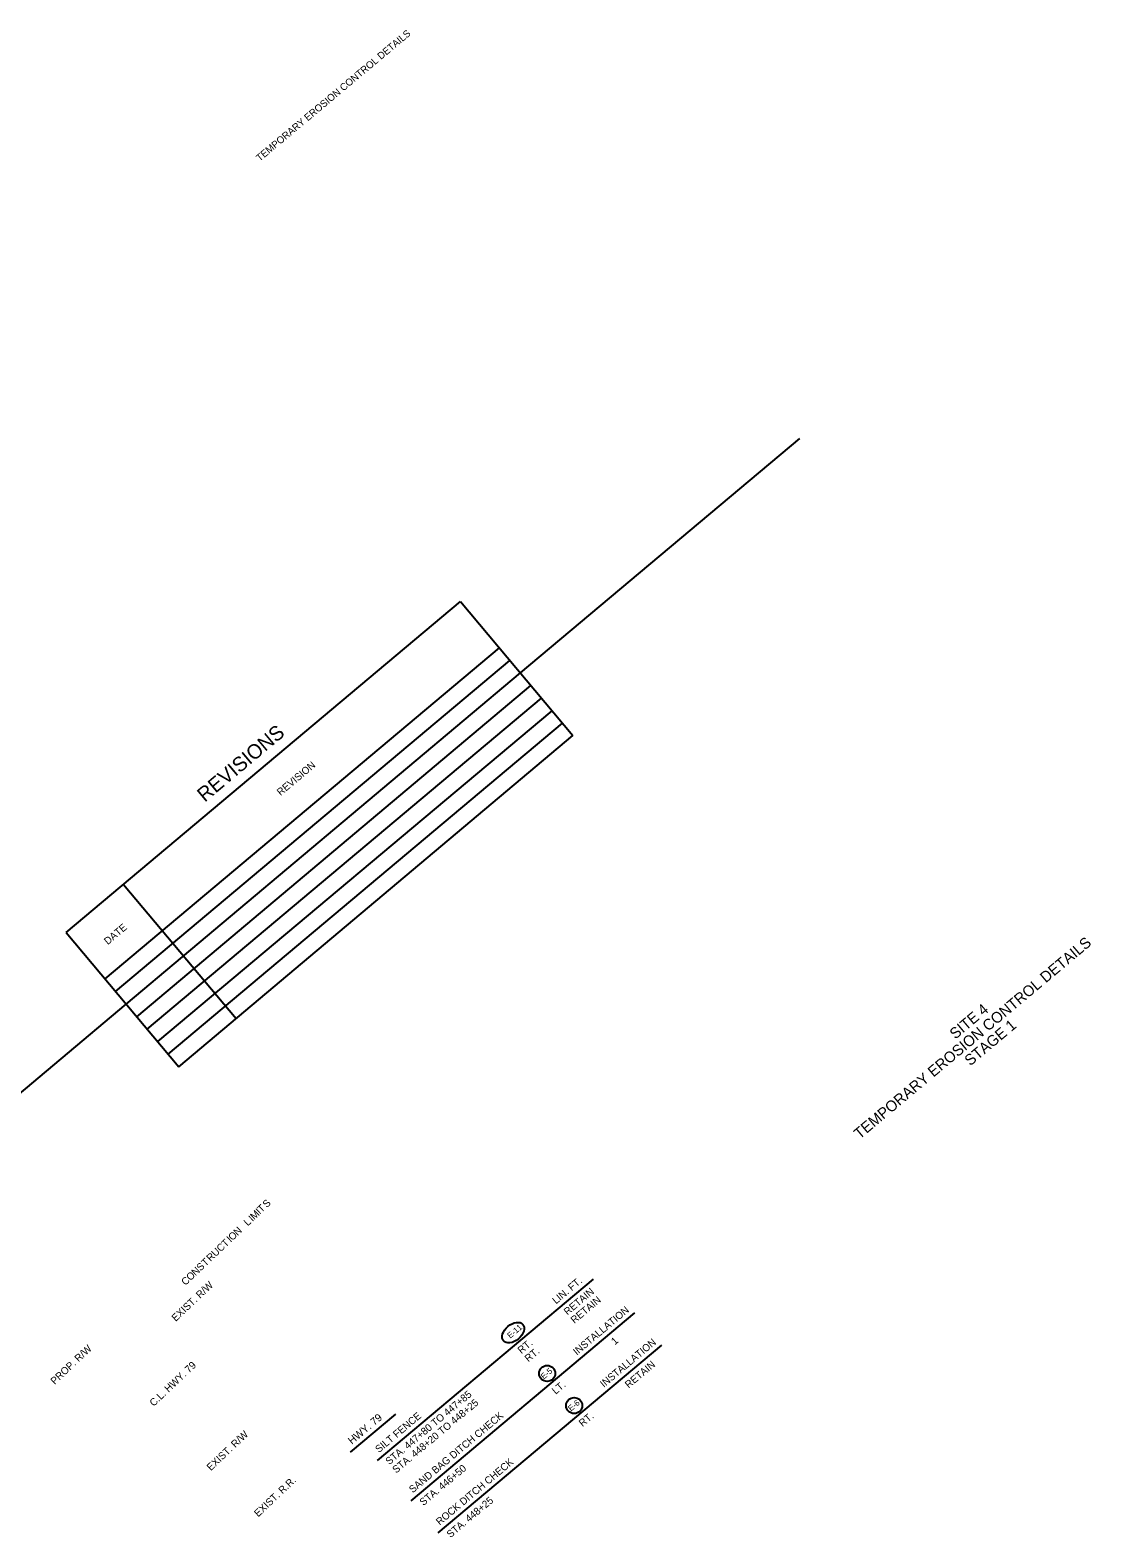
# Model space of a CAD drawing. Extents: x 1430270 to 1431940, y 1964864 to 1966264.
# Drawn here: x 1431064 to 1431940, y 1965020 to 1966264 of the extents above; entities that cross this region are included whole.
import ezdxf

# ---------------------------------------------------------------- set-up
doc = ezdxf.new("R2010")
doc.units = 0
for name, color, linetype in [('1', 7, 'Continuous'), ('44', 7, 'Continuous'), ('60', 7, 'Continuous'), ('Default', 7, 'Continuous'), ('R_Draft', 7, 'Continuous')]:
    doc.layers.add(name, color=color, linetype=linetype)

msp = doc.modelspace()

# ---------------------------------------------------------------- linework, layer by layer
at = {"layer": '1'}
for p, q in [((1431469.3, 1965733.3), (1431699.9, 1965926.7)), ((1430924.6, 1965276.1), (1431143.8, 1965460.1))]:
    msp.add_line(p, q, dxfattribs=at)
for centre in [(1431491.4, 1965155.3), (1431513.7, 1965128.8)]:
    msp.add_circle(centre, 6.61, dxfattribs=at)
msp.add_ellipse((1431463.3, 1965189), major_axis=(8.06, 6.76), ratio=0.638788, dxfattribs=at)
at = {"layer": '44'}
for p, q in [((1431351.3, 1965083.6), (1431529.6, 1965233.2)), ((1431379.1, 1965050.3), (1431563.8, 1965205.3)), ((1431401.4, 1965023.8), (1431586, 1965178.7)), ((1431328.9, 1965090.4), (1431366.4, 1965121.8))]:
    msp.add_line(p, q, dxfattribs=at)
at = {"layer": 'Default'}
for p, q in [((1431094.3, 1965519.1), (1431419.9, 1965792.3)), ((1431419.9, 1965792.3), (1431512.7, 1965681.6)), ((1431126.4, 1965480.8), (1431452, 1965754)), ((1431135.1, 1965470.4), (1431460.7, 1965743.6)), ((1431143.8, 1965460.1), (1431469.3, 1965733.3)), ((1431152.5, 1965449.7), (1431478, 1965722.9)), ((1431152.5, 1965449.7), (1431478, 1965722.9)), ((1431161.1, 1965439.4), (1431486.7, 1965712.6)), ((1431169.8, 1965429.1), (1431495.4, 1965702.2)), ((1431178.5, 1965418.7), (1431504.1, 1965691.9)), ((1431187.2, 1965408.4), (1431512.7, 1965681.6)), ((1431141.6, 1965558.8), (1431234.5, 1965448.1)), ((1431094.3, 1965519.1), (1431187.2, 1965408.4))]:
    msp.add_line(p, q, dxfattribs=at)

# ---------------------------------------------------------------- texts
at = {"layer": '1'}
for s, height, p in [('TEMPORARY EROSION CONTROL DETAILS', 5.862, (1431254.1, 1966155.1)), ('E-11', 4.8, (1431460.9, 1965183.9)), ('E-5 ', 4.8, (1431488.6, 1965150.2)), ('E-6 ', 4.8, (1431511.1, 1965123.8))]:
    msp.add_text(s, height=height, rotation=40, dxfattribs=at).set_placement(p)
at = {"layer": '44'}
for s, height, p in [('LIN. FT.', 6, (1431498.7, 1965212.2)), ('RETAIN', 6, (1431508.2, 1965203)), ('RETAIN', 6, (1431513.9, 1965196.1)), ('INSTALLATION', 6, (1431515.9, 1965170)), ('RT.', 6, (1431470.1, 1965171.2)), ('INSTALLATION', 6, (1431538.2, 1965143.4)), ('1', 6, (1431547.3, 1965178.5)), ('RT.', 6, (1431475.9, 1965164.4)), ('RETAIN', 6, (1431558.7, 1965142.8)), ('LT.', 6, (1431498.4, 1965137.7)), ('STA. 447+80 TO 447+85', 6, (1431361, 1965079.5)), ('STA. 448+20 TO 448+25', 6, (1431366.7, 1965072.6)), ('HWY. 79', 6.25, (1431330.2, 1965096.4)), ('SILT FENCE      ', 6, (1431352.5, 1965089.5)), ('SAND BAG DITCH CHECK', 6, (1431380.4, 1965056.3)), ('RT.', 6, (1431520.6, 1965111)), ('ROCK DITCH CHECK', 6, (1431402.7, 1965029.7)), ('STA. 446+50', 6, (1431389.2, 1965045.8)), ('STA. 448+25', 6, (1431411.5, 1965019.3))]:
    msp.add_text(s, height=height, rotation=40, dxfattribs=at).set_placement(p)
at = {"layer": '60'}
for s, p in [('TEMPORARY EROSION CONTROL DETAILS', (1431749.4, 1965348.2)), ('SITE 4', (1431828.4, 1965430.6)), ('STAGE 1', (1431840.7, 1965408.6))]:
    msp.add_text(s, height=9, rotation=40, dxfattribs=at).set_placement(p)
at = {"layer": 'Default'}
for s, height, p in [('REVISIONS', 12, (1431208.7, 1965626.2)), ('REVISION', 6, (1431271.3, 1965631.7)), ('DATE', 6, (1431128.6, 1965508.7))]:
    msp.add_text(s, height=height, rotation=40, dxfattribs=at).set_placement(p)
at = {"layer": 'R_Draft'}
for s, rotation, p in [('T', 43.7996, (1431255.6, 1965287.6)), ('S', 43.7996, (1431259.9, 1965291.6)), ('L', 43.3076, (1431244.2, 1965276.6)), ('I', 44.0457, (1431248.2, 1965280.3)), ('M', 44.0457, (1431249.6, 1965281.7)), ('I', 44.0457, (1431254.2, 1965286.2)), ('T', 43.4783, (1431225.9, 1965259.1)), ('I', 43.4783, (1431230.1, 1965263.2)), ('O', 43.4783, (1431231.5, 1965264.5)), ('N', 43.8792, (1431235.8, 1965268.6)), ('R', 43.8898, (1431213.5, 1965247.3)), ('U', 43.8898, (1431217.6, 1965251.2)), ('C', 43.5785, (1431221.8, 1965255.2)), ('N', 43.5726, (1431201.1, 1965235.5)), ('S', 43.6066, (1431205.2, 1965239.4)), ('T', 43.6066, (1431209.3, 1965243.3)), ('EXIST. R/W', 43.366, (1431184.7, 1965197.8)), ('C', 43.5245, (1431192.7, 1965227.5)), ('O', 43.5726, (1431196.8, 1965231.4)), ('PROP. R/W', 43.366, (1431084.8, 1965145.7)), ('C.L. HWY. 79', 43.4244, (1431166.5, 1965127.7)), ('EXIST. R/W', 43.366, (1431213.7, 1965074.6)), ('EXIST. R.R.', 43.3919, (1431252.8, 1965036.5))]:
    msp.add_text(s, height=6, rotation=rotation, dxfattribs=at).set_placement(p)

doc.saveas('drawing.dxf')
